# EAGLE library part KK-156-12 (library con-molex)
KK 156 HEADER Source: http://www.molex.com/pdm_docs/sd/026604100_sd.pdf
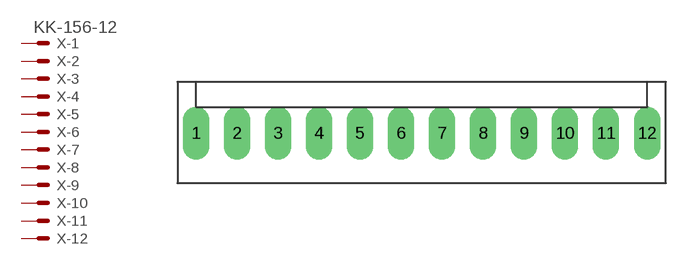
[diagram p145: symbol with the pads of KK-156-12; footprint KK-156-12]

Designator prefix X; gates -1=MV -2=M -3=M -4=M -5=M -6=M -7=M -8=M -9=M -10=M -11=M -12=M

## KK-156-12 (OC_FARNELL: unknown; OC_NEWARK: unknown)  [KK-156-12]
1  -1:S  pas
2  -2:S  pas
3  -3:S  pas
4  -4:S  pas
5  -5:S  pas
6  -6:S  pas
7  -7:S  pas
8  -8:S  pas
9  -9:S  pas
10  -10:S  pas
11  -11:S  pas
12  -12:S  pas

## Footprint KK-156-12 (pad centres in mm)
KK 156 HEADER Source: http://www.molex.com/pdm_docs/sd/026604100_sd.pdf
drill 1.7 pad 2.184 long: 1 -21.78,0; 2 -17.82,0; 3 -13.86,0; 4 -9.9,0; 5 -5.94,0; 6 -1.98,0; 7 1.98,0; 8 5.94,0; 9 9.9,0; 10 13.86,0; 11 17.82,0; 12 21.78,0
